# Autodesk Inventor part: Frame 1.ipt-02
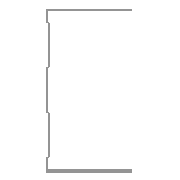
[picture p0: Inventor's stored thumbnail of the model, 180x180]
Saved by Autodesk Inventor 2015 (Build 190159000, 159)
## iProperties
Created: 2015-04
Part Number: Frame 1.ipt-02
Material: Aluminum 6061
Document SubType Name: Modeling
Designer: suporte
Density: 2.7 g/cm^3
Appearance: Aluminum - Flat
Categories: <MemberInstance><Categories><Category DisplayName="Structural Shapes" InternalName="089c4875-fa83-4c05-b084-43b9cc11f5ed" Mnemonic="GRDR"><CategoryParameter Dis
G_L: 2100,000 mm
Author: suporte
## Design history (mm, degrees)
node "Start Plane"
node "End Plane"
sketch "Sketch1"
  geometry: L1 (24.7, 37.5)-(24.7, 36.9); L2 (24.7, 36.9)-(-24.7, 36.9); L3 (-24.7, -36.9)-(24.7, -36.9); L4 (24.7, -36.9)-(24.7, -37.5); L5 (24.7, -37.5)-(-25.3, -37.5); L6 (-25.3, 37.5)-(24.7, 37.5); L7 (-24.7, 36.9)-(-24.7, 31.9); L8 (-24.7, 31.9)-(-23.3, 30.5); L9 (-23.3, 30.5)-(-23.3, 10.934); L10 (-23.3, 10.934)-(-24.7, 9.534); L11 (-24.7, 9.534)-(-24.7, -9.534); L12 (-24.7, -9.534)-(-23.3, -10.934); L13 (-23.3, -10.934)-(-23.3, -30.5); L14 (-23.3, -30.5)-(-24.7, -31.9); L15 (-24.7, -31.9)-(-24.7, -36.9); L16 (-25.3, -37.5)-(-25.3, -31.651); L17 (-25.3, -31.651)-(-23.9, -30.251); L18 (-23.9, -30.251)-(-23.9, -11.183); L19 (-23.9, -11.183)-(-25.3, -9.783); L20 (-25.3, -9.783)-(-25.3, 9.783); L21 (-25.3, 9.783)-(-23.9, 11.183); L22 (-23.9, 11.183)-(-23.9, 30.251); L23 (-23.9, 30.251)-(-25.3, 31.651); L24 (-25.3, 31.651)-(-25.3, 37.5); L25 (-25.3, 0)-(30.37, 0); 3 further points
  constraints: 50 end point, 10 point on line, 9 parallel, 5 perpendicular, 4 equal length, 3 midpoint, 3 vertical, 2 vertical alignment, 1 collinear, 1 horizontal, 1 horizontal alignment
  dimensions: "d3" = 0.6 distance of L1.start L1.end (= d6); "d5" = 75 distance between parallel lines of L5 L6; "d6" = 0.6 distance between parallel lines of L24 L7 (= d8); "d7" = 0.6 distance between parallel lines of L8 L23 (= d8); "d8" = 0.6 distance between parallel lines of L22 L9 (= d12); "Espessura" = 0.6 distance between parallel lines of L17 L14; "d10" = 0.6 distance between parallel lines of L13 L18 (= Espessura); "d11" = 0.6 distance between parallel lines of L12 L19 (= Espessura); "d12" = 0.6 distance between parallel lines of L21 L10 (= d11); "d13" = 5 distance of L2.end L7.end; "d15" = 135 deg angle of L9 L8; "d16" = 2 distance between parallel lines of L24 L9; "d17" = 50 distance of L6.start L1.start
extrude "Body" join sketch "Sketch1" stored distance "d24" = 0.13; taper "d25" = 0 deg
node "Driven Length"
  sketch "Sketch10"
    geometry: L1 (0, 0)-(10, 0) reference
    constraints: 2 end point, 1 horizontal
  workplane "Work Plane7"
  sketch "Sketch11"
    geometry: L1 (-35.3, 0)-(34.7, 0) reference; L2 (-35.3, 2100)-(34.7, 2100) reference
    dimensions: "d27" = 2100 distance between parallel lines of L1 L2 (derived)
body "Solid1"
other parameters: "G_OFFSET_START" = 0 [user parameter; used in 1 equation term], "G_OFFSET_END" = 0 [user parameter; used in 1 equation term], "d22" = 0 (computed from G_OFFSET_START), "G_L" = 2100 (= d27) [user parameter], "d34" = 90 deg
